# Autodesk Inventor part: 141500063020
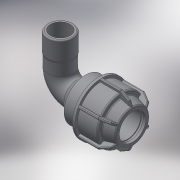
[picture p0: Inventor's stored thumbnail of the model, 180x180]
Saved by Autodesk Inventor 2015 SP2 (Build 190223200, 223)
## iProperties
Created: 2017-08
Part Number: 141500063020
Material: Generic
Description: L.14 90° ELBOW FEMALE ADAPTOR (SILVER) 63-2"
Document SubType Name: Modeling
Designer: KIM
Density: 1 g/cm^3
Appearance: Default
Author: KIM
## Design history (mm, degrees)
derived "141500.ipt"
feature "Solid1::141500.ipt"
feature "Solid2::141500.ipt"
tag "TaggingFeature1"
body "Solid1"
body "Solid2"
other parameters: "d1" = 63, "d2" = 82, "d4" = 15 deg, "d5" = 54.12, "d6" = 17.8596, "d10" = 106, "d16" = 64.26, "d17" = 4.1, "d22" = 100.8, "d24" = 4.1, "d25" = 95.4, "d26" = 79.5, "d27" = 4.1, "d28" = 135 deg, "d29" = 2.46, "d31" = 3.15, "d46" = 150 deg, "d49" = 5.3, "d50" = 0, "d58" = 1.89, "d61" = 360 deg, "d63" = 56.7, "d94" = 86, "d95" = 56.656, "d96" = 73.6528, "d98" = 45.3248, "d99" = 66.28752, "d100" = 135 deg, "d108" = 3.15, "d112" = 39, "d113" = 115, "d114" = 83.64, "d115" = 66.28752, "d116" = 45 deg, "d117" = 0, "d118" = 0, "d_" = 63, "G_" = 56.656, "E_" = 106, "A_" = 115, "l_" = 82, "A_1" = 86
